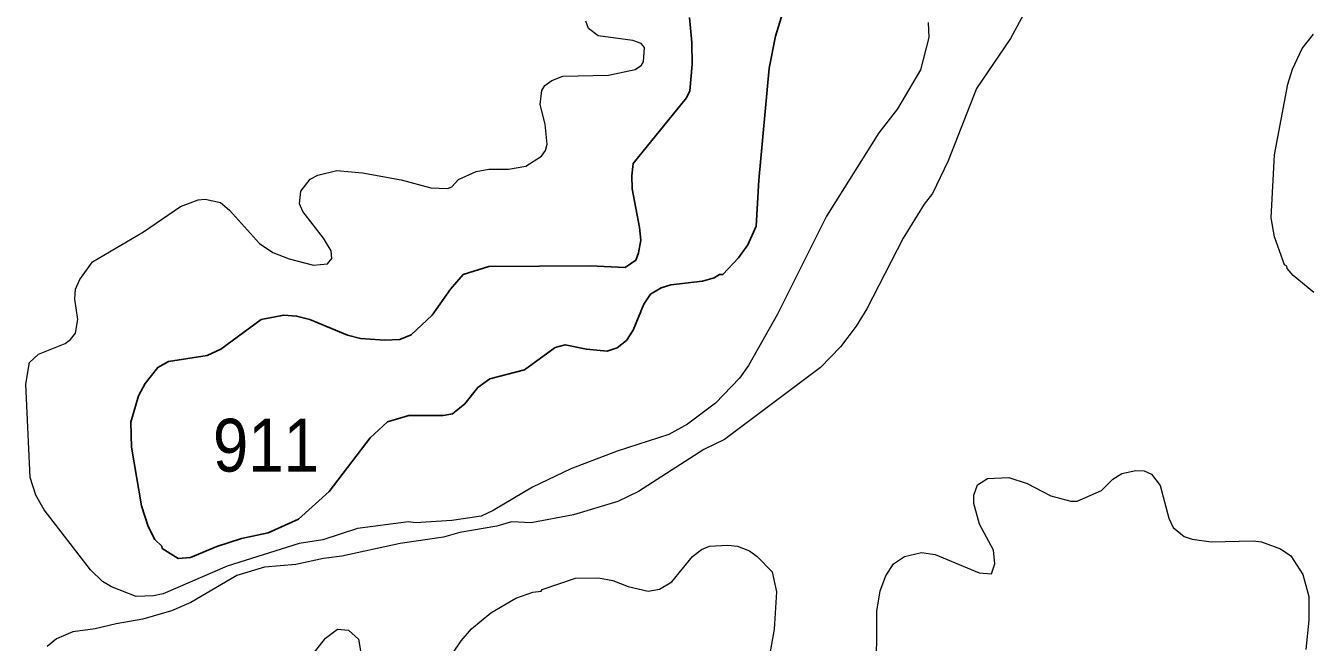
# Model space of a CAD drawing. Extents: x 598.3 to 623.2, y 6902.2 to 6930.1.
# Drawn here: x 604.979 to 606.927, y 6927.958 to 6928.893 of the extents above; entities that cross this region are included whole.
import ezdxf

# ---------------------------------------------------------------- set-up
doc = ezdxf.new("R2010")
doc.units = 0
doc.header["$LTSCALE"] = 0.032
doc.layers.add('1', color=7, linetype='Continuous', lineweight=25)
doc.layers.add('2', color=7, linetype='Continuous', lineweight=13)
doc.layers.add('21', color=7, linetype='Continuous')

msp = doc.modelspace()

# ---------------------------------------------------------------- linework, layer by layer
at = {"layer": '1'}
for points in [[(606.1265, 6928.9128), (606.115, 6928.8769), (606.1054, 6928.8286), (606.09, 6928.659), (606.0859, 6928.5888), (606.0734, 6928.5607), (606.0594, 6928.5412), (606.0355, 6928.5159), (606.0303, 6928.5158), (606.0221, 6928.5107), (606.0046, 6928.5054), (605.9568, 6928.5001), (605.9421, 6928.4957), (605.9259, 6928.4861), (605.9156, 6928.4706), (605.8996, 6928.4314), (605.8894, 6928.4158), (605.8752, 6928.4048), (605.8603, 6928.3993), (605.8288, 6928.4025), (605.7968, 6928.4089), (605.7814, 6928.4051), (605.7349, 6928.3711), (605.6825, 6928.3576), (605.6645, 6928.3446), (605.6444, 6928.3197), (605.6261, 6928.3046), (605.6118, 6928.3022), (605.5597, 6928.3021), (605.5275, 6928.2924), (605.5014, 6928.2681), (605.4393, 6928.1866), (605.3925, 6928.145), (605.3468, 6928.1243), (605.3065, 6928.1157), (605.269, 6928.1033), (605.2292, 6928.0868), (605.2103, 6928.0853), (605.186, 6928.1004), (605.1855, 6928.104), (605.1751, 6928.1138), (605.1651, 6928.1338), (605.1548, 6928.1648)], [(605.1548, 6928.1648), (605.1396, 6928.2539), (605.1388, 6928.2921), (605.1503, 6928.3316), (605.1605, 6928.3505), (605.1793, 6928.3749), (605.1958, 6928.384), (605.2545, 6928.3931), (605.2748, 6928.4025), (605.3361, 6928.4476), (605.3703, 6928.4543), (605.3897, 6928.4527), (605.4099, 6928.4476), (605.4669, 6928.4238), (605.4866, 6928.4188), (605.5233, 6928.4163), (605.5459, 6928.4174), (605.5635, 6928.4242), (605.595, 6928.4541), (605.6231, 6928.4935), (605.6422, 6928.5156), (605.6812, 6928.5279), (605.8343, 6928.5289), (605.8873, 6928.5266), (605.9035, 6928.5375), (605.9079, 6928.5485), (605.911, 6928.5679), (605.9094, 6928.5871), (605.8981, 6928.6457), (605.8974, 6928.6655), (605.8998, 6928.6842), (605.9806, 6928.7838), (605.9856, 6928.7942), (605.9888, 6928.8343), (605.9887, 6928.8674), (605.9848, 6928.9053)]]:
    msp.add_lwpolyline(points, dxfattribs=at)
at = {"layer": '2'}
for points in [[(606.4938, 6928.9157), (606.4711, 6928.8734), (606.4196, 6928.7977), (606.3769, 6928.6883), (606.3529, 6928.6387), (606.3403, 6928.6226), (606.3084, 6928.5707), (606.2537, 6928.4639), (606.2375, 6928.4373), (606.2137, 6928.4063), (606.1835, 6928.3747), (606.0379, 6928.2656), (606.0064, 6928.2502), (605.9076, 6928.187), (605.8763, 6928.1714), (605.8094, 6928.1516), (605.7452, 6928.1395), (605.7152, 6928.141), (605.6932, 6928.1343), (605.6369, 6928.1247), (605.6123, 6928.1173), (605.5468, 6928.1078), (605.4583, 6928.0885), (605.4305, 6928.0852), (605.3888, 6928.0762), (605.3412, 6928.0722), (605.2992, 6928.0592), (605.2293, 6928.0187), (605.2001, 6928.0058), (605.1569, 6927.993), (605.1162, 6927.9864), (605.0844, 6927.9784), (605.0509, 6927.9742), (605.026, 6927.9632), (605.0121, 6927.952)], [(604.9946, 6928.181), (604.9859, 6928.2079), (604.9794, 6928.3497), (604.9849, 6928.3824), (604.999, 6928.3949), (605.0393, 6928.4112), (605.0474, 6928.4173), (605.0546, 6928.427), (605.0585, 6928.4473), (605.0539, 6928.4784), (605.0547, 6928.4936), (605.0613, 6928.508), (605.0804, 6928.5351), (605.1577, 6928.5803), (605.2138, 6928.6189), (605.2408, 6928.6291), (605.2511, 6928.6299), (605.2747, 6928.6251), (605.2881, 6928.6135), (605.3338, 6928.5628), (605.3539, 6928.5492), (605.3783, 6928.5397), (605.4154, 6928.5297), (605.4365, 6928.532), (605.443, 6928.5402), (605.4422, 6928.5516), (605.4304, 6928.5707), (605.399, 6928.6113), (605.3939, 6928.6231), (605.3963, 6928.6421), (605.4105, 6928.6605), (605.422, 6928.6664), (605.4506, 6928.6736), (605.4896, 6928.6697), (605.5482, 6928.6592), (605.5932, 6928.647), (605.6184, 6928.6462), (605.6247, 6928.6488), (605.6351, 6928.6599), (605.662, 6928.6721), (605.681, 6928.6753), (605.7109, 6928.6754), (605.737, 6928.6801), (605.7605, 6928.6949), (605.7669, 6928.7038), (605.7693, 6928.7131), (605.7662, 6928.7439), (605.7589, 6928.7735), (605.761, 6928.7949), (605.766, 6928.8023), (605.7765, 6928.81), (605.7932, 6928.8162), (605.8622, 6928.8177), (605.9028, 6928.8266), (605.9123, 6928.8329), (605.9151, 6928.8384), (605.9167, 6928.8597), (605.9119, 6928.8662), (605.8992, 6928.8705), (605.8464, 6928.8778), (605.8318, 6928.8885), (605.8277, 6928.8996)], [(606.3463, 6928.8977), (606.3473, 6928.8753), (606.3348, 6928.8261), (606.2998, 6928.7671), (606.2717, 6928.7307), (606.1924, 6928.6044), (606.1181, 6928.4557), (606.0744, 6928.378), (606.0608, 6928.3588), (606.0244, 6928.3207), (605.9821, 6928.289), (605.9534, 6928.273), (605.8754, 6928.2479), (605.8053, 6928.2209), (605.7473, 6928.1935), (605.6874, 6928.1579), (605.6692, 6928.1495), (605.6251, 6928.143), (605.5698, 6928.1395), (605.5592, 6928.1409), (605.482, 6928.1305), (605.4296, 6928.1137), (605.3936, 6928.108), (605.2845, 6928.0738), (605.1877, 6928.0318), (605.1728, 6928.0286), (605.1467, 6928.0278), (605.1093, 6928.042), (605.0957, 6928.0505), (605.0775, 6928.068), (605.0072, 6928.159), (604.9946, 6928.181)], [(606.9308, 6928.4885), (606.8996, 6928.514), (606.8902, 6928.525), (606.8897, 6928.5285), (606.8863, 6928.5302), (606.8711, 6928.5729), (606.8663, 6928.6016), (606.8711, 6928.697), (606.8914, 6928.8043), (606.8985, 6928.8268), (606.9129, 6928.8585), (606.9302, 6928.8801)], [(606.2681, 6927.8988), (606.2689, 6928.0052), (606.2737, 6928.0364), (606.2824, 6928.0587), (606.294, 6928.0769), (606.3106, 6928.0881), (606.3362, 6928.0942), (606.3573, 6928.0913), (606.4237, 6928.0635), (606.4424, 6928.0621), (606.4477, 6928.0771), (606.4454, 6928.0979), (606.4241, 6928.1373), (606.4155, 6928.1684), (606.4155, 6928.1812), (606.4213, 6928.1971), (606.4362, 6928.2067), (606.4686, 6928.2081), (606.4966, 6928.1988), (606.5321, 6928.1804), (606.5626, 6928.1723), (606.5724, 6928.1719), (606.609, 6928.1882), (606.6263, 6928.2055), (606.6398, 6928.2139), (606.6612, 6928.2186), (606.6738, 6928.2179), (606.6848, 6928.2131), (606.6977, 6928.1961), (606.7113, 6928.1461), (606.7174, 6928.1323), (606.7344, 6928.1188), (606.7462, 6928.1144), (606.7751, 6928.1105), (606.8388, 6928.112), (606.8515, 6928.1104), (606.8803, 6928.1), (606.896, 6928.0894), (606.9139, 6928.0612), (606.9229, 6928.0275), (606.9229, 6927.9918), (606.9188, 6927.947)], [(605.6001, 6927.9028), (605.639, 6927.9605), (605.6547, 6927.9787), (605.6841, 6928.003), (605.7221, 6928.025), (605.7478, 6928.0343), (605.7603, 6928.0359), (605.7616, 6928.0382), (605.8123, 6928.0552), (605.8469, 6928.056), (605.8687, 6928.0521), (605.8922, 6928.043), (605.9224, 6928.0359), (605.9396, 6928.0385), (605.9582, 6928.0497), (605.9893, 6928.088), (606.0032, 6928.0986), (606.015, 6928.1039), (606.0428, 6928.1055), (606.0574, 6928.1037), (606.0757, 6928.0968), (606.0875, 6928.0884), (606.1102, 6928.0648), (606.1166, 6928.0345), (606.1134, 6927.9781), (606.1053, 6927.9327)], [(605.4097, 6927.9341), (605.4335, 6927.9646), (605.4516, 6927.9783), (605.4683, 6927.9767), (605.4836, 6927.9628), (605.4893, 6927.9301)]]:
    msp.add_lwpolyline(points, dxfattribs=at)

# ---------------------------------------------------------------- texts
at = {"layer": '21', "width": 0.9}
msp.add_text('911', height=0.08, dxfattribs=at).set_placement((605.263, 6928.217))

doc.saveas('drawing.dxf')
